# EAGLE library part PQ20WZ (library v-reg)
VOLTAGE REGULATOR Sharp PQ20WZ51 / PQ20WZ11
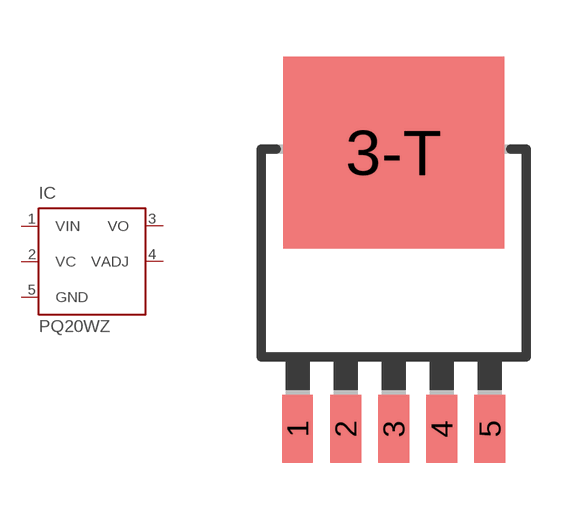
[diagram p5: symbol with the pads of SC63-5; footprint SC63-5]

Designator prefix IC

## PQ20WZ  [SC63-5]
1  VIN  in
2  VC  in
3  VO  out
3-T  VO-3  out
4  VADJ  pas
5  GND  pwr

## Footprint SC63-5 (pad centres in mm)
SO63-5 Sharp
smd 0.813 x 1.8: 1 -2.54,-5.397; 2 -1.27,-5.397; 3 0,-5.397; 4 1.27,-5.397; 5 2.54,-5.397
smd 5.842 x 5.08: 3-T 0,1.905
